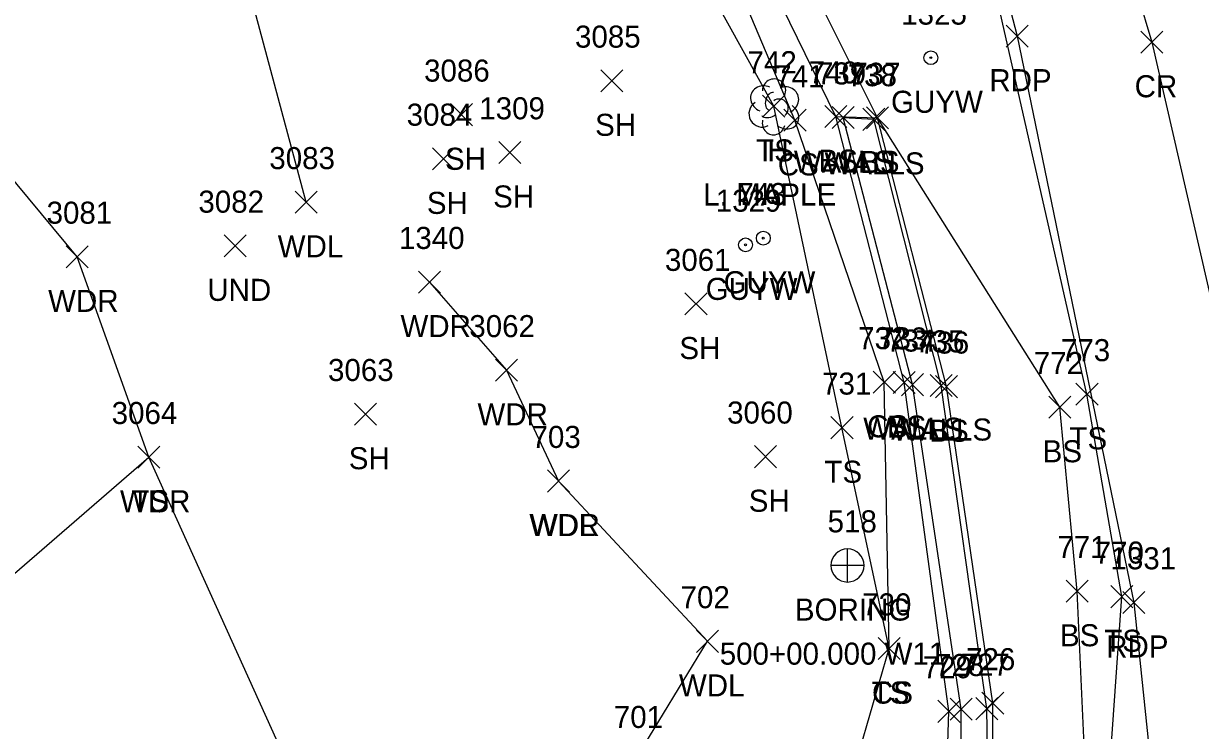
# Model space of a CAD drawing. Extents: x 1509053 to 1511576, y 400838 to 402572.
# Drawn here: x 1509685.4 to 1509792.1, y 401650.1 to 401714.2 of the extents above; entities that cross this region are included whole.
import ezdxf

# ---------------------------------------------------------------- set-up
doc = ezdxf.new("R2010")
doc.units = 0
for name, color, linetype in [('D_A', 7, 'Continuous'), ('D_I', 7, 'Continuous'), ('D_TIC', 7, 'Continuous'), ('G_A', 7, 'Continuous'), ('G_C', 7, 'Continuous'), ('G_I', 7, 'Continuous'), ('GA_P', 7, 'Continuous'), ('L_A', 7, 'Continuous'), ('L_C', 7, 'Continuous'), ('L_I', 7, 'Continuous'), ('L_TIC', 7, 'Continuous'), ('LAWA', 7, 'Continuous'), ('LELB', 7, 'Continuous'), ('LTD', 7, 'Continuous'), ('LWS', 7, 'Continuous'), ('P_A', 7, 'Continuous'), ('P_I', 7, 'Continuous'), ('P_TIC', 7, 'Continuous'), ('PET', 7, 'Continuous'), ('PRC', 7, 'Continuous'), ('U_A', 7, 'Continuous'), ('U_I', 7, 'Continuous'), ('UPGW', 7, 'Continuous')]:
    doc.layers.add(name, color=color, linetype=linetype)

msp = doc.modelspace()

# ---------------------------------------------------------------- linework, layer by layer
at = {"layer": 'D_TIC'}
for points in [[(1509703.59, 401693.05), (1509705.59, 401695.05)], [(1509705.59, 401693.05), (1509703.59, 401695.05)]]:
    msp.add_lwpolyline(points, dxfattribs=at)
at = {"layer": 'GA_P'}
for p, q in [((1509760.09, 401665.05), (1509760.09, 401666.55)), ((1509760.09, 401665.05), (1509758.59, 401665.05)), ((1509761.59, 401665.05), (1509760.09, 401665.05)), ((1509760.09, 401663.55), (1509760.09, 401665.05))]:
    msp.add_line(p, q, dxfattribs=at)
for start, end in [(90, 180), (0, 90), (180, 270), (270, 0)]:
    msp.add_arc((1509760.09, 401665.05), 1.5, start, end, dxfattribs=at)
at = {"layer": 'L_TIC'}
for points in [[(1509737.72, 401708.02), (1509739.72, 401710.02)], [(1509739.72, 401708.02), (1509737.72, 401710.02)], [(1509724.11, 401704.94), (1509726.11, 401706.94)], [(1509726.11, 401704.94), (1509724.11, 401706.94)], [(1509752.4, 401705.7), (1509754.4, 401707.7)], [(1509754.4, 401705.7), (1509752.4, 401707.7)], [(1509758.03, 401704.77), (1509760.03, 401706.77)], [(1509760.03, 401704.77), (1509758.03, 401706.77)], [(1509754.33, 401704.43), (1509756.33, 401706.43)], [(1509756.33, 401704.43), (1509754.33, 401706.43)], [(1509758.69, 401704.68), (1509760.69, 401706.68)], [(1509760.69, 401704.68), (1509758.69, 401706.68)], [(1509761.47, 401704.52), (1509763.47, 401706.52)], [(1509763.47, 401704.52), (1509761.47, 401706.52)], [(1509761.8, 401704.65), (1509763.8, 401706.65)], [(1509763.8, 401704.65), (1509761.8, 401706.65)], [(1509722.47, 401700.94), (1509724.47, 401702.94)], [(1509724.47, 401700.94), (1509722.47, 401702.94)], [(1509728.49, 401701.52), (1509730.49, 401703.52)], [(1509730.49, 401701.52), (1509728.49, 401703.52)], [(1509710.02, 401697), (1509712.02, 401699)], [(1509712.02, 401697), (1509710.02, 401699)], [(1509689.26, 401692.05), (1509691.26, 401694.05)], [(1509691.26, 401692.05), (1509689.26, 401694.05)], [(1509721.2, 401689.76), (1509723.2, 401691.76)], [(1509723.2, 401689.76), (1509721.2, 401691.76)], [(1509745.36, 401687.77), (1509747.36, 401689.77)], [(1509747.36, 401687.77), (1509745.36, 401689.77)], [(1509728.19, 401681.76), (1509730.19, 401683.76)], [(1509730.19, 401681.76), (1509728.19, 401683.76)], [(1509762.43, 401680.67), (1509764.43, 401682.67)], [(1509764.43, 401680.67), (1509762.43, 401682.67)], [(1509764.23, 401680.64), (1509766.23, 401682.64)], [(1509766.23, 401680.64), (1509764.23, 401682.64)], [(1509764.98, 401680.45), (1509766.98, 401682.45)], [(1509766.98, 401680.45), (1509764.98, 401682.45)], [(1509767.59, 401680.38), (1509769.59, 401682.38)], [(1509769.59, 401680.38), (1509767.59, 401682.38)], [(1509768.07, 401680.27), (1509770.07, 401682.27)], [(1509770.07, 401680.27), (1509768.07, 401682.27)], [(1509780.8, 401679.58), (1509782.8, 401681.58)], [(1509782.8, 401679.58), (1509780.8, 401681.58)], [(1509778.34, 401678.41), (1509780.34, 401680.41)], [(1509780.34, 401678.41), (1509778.34, 401680.41)], [(1509715.39, 401677.78), (1509717.39, 401679.78)], [(1509717.39, 401677.78), (1509715.39, 401679.78)], [(1509758.59, 401676.55), (1509760.59, 401678.55)], [(1509760.59, 401676.55), (1509758.59, 401678.55)], [(1509695.77, 401673.88), (1509697.77, 401675.88)], [(1509697.77, 401673.88), (1509695.77, 401675.88)], [(1509695.77, 401673.88), (1509697.77, 401675.88)], [(1509697.77, 401673.88), (1509695.77, 401675.88)], [(1509751.65, 401673.92), (1509753.65, 401675.92)], [(1509753.65, 401673.92), (1509751.65, 401675.92)], [(1509732.89, 401671.71), (1509734.89, 401673.71)], [(1509734.89, 401671.71), (1509732.89, 401673.71)], [(1509732.89, 401671.71), (1509734.89, 401673.71)], [(1509734.89, 401671.71), (1509732.89, 401673.71)], [(1509779.91, 401661.72), (1509781.91, 401663.72)], [(1509781.91, 401661.72), (1509779.91, 401663.72)], [(1509783.95, 401661.22), (1509785.95, 401663.22)], [(1509785.95, 401661.22), (1509783.95, 401663.22)], [(1509746.4, 401657.17), (1509748.4, 401659.17)], [(1509748.4, 401657.17), (1509746.4, 401659.17)], [(1509762.87, 401656.52), (1509764.87, 401658.52)], [(1509764.87, 401656.52), (1509762.87, 401658.52)], [(1509762.87, 401656.52), (1509764.87, 401658.52)], [(1509764.87, 401656.52), (1509762.87, 401658.52)], [(1509772.26, 401651.55), (1509774.26, 401653.55)], [(1509774.26, 401651.55), (1509772.26, 401653.55)], [(1509768.29, 401650.82), (1509770.29, 401652.82)], [(1509770.29, 401650.82), (1509768.29, 401652.82)], [(1509769.39, 401651.02), (1509771.39, 401653.02)], [(1509771.39, 401651.02), (1509769.39, 401653.02)], [(1509771.72, 401651.06), (1509773.72, 401653.06)], [(1509773.72, 401651.06), (1509771.72, 401653.06)]]:
    msp.add_lwpolyline(points, dxfattribs=at)
at = {"layer": 'LAWA'}
for points in [[(1509638.88, 401488.13), (1509666.35, 401492.77), (1509693.47, 401489.31), (1509706.73, 401489.66), (1509714.33, 401510.79), (1509715.13, 401545.88), (1509713.34, 401580.23), (1509712.38, 401615.78), (1509710.87, 401643.63), (1509696.77, 401674.88), (1509690.26, 401693.05), (1509667.45, 401720.56), (1509662.48, 401743.44), (1509649.82, 401764.29), (1509628.65, 401784.18), (1509611.29, 401798.2), (1509592.85, 401815.68), (1509576.11, 401831.25), (1509568.72, 401841.78), (1509569.85, 401855.18), (1509582.24, 401868.06), (1509599.14, 401876.59), (1509619.4, 401883.23)], [(1509711.02, 401698), (1509703.28, 401726.89), (1509691.85, 401755.8), (1509687.42, 401782.25), (1509686, 401801.39)], [(1509722.21, 401690.76), (1509729.19, 401682.76), (1509733.89, 401672.71)], [(1509726.93, 401491.97), (1509738.87, 401505.78), (1509741.65, 401534.19), (1509742.92, 401557.34), (1509741.39, 401578.09), (1509745.24, 401603.86), (1509743.92, 401621.55), (1509740.79, 401647.31), (1509747.4, 401658.17), (1509733.89, 401672.71)]]:
    msp.add_lwpolyline(points, dxfattribs=at)
at = {"layer": 'LELB'}
for points in [[(1509773.23, 401624.44), (1509773.26, 401652.55), (1509769.07, 401681.27), (1509762.8, 401705.65), (1509755.11, 401721.11), (1509758.06, 401721.61), (1509756.54, 401726.82), (1509750.91, 401752.16), (1509738, 401786.77), (1509724.07, 401817.58), (1509715.24, 401833.65), (1509705.02, 401848.12), (1509687.56, 401874.43), (1509682.95, 401881.5), (1509682.01, 401883.09), (1509678.34, 401883.46), (1509668.76, 401883.33)], [(1509755.23, 401531.03), (1509759.29, 401552.77), (1509765.02, 401573.72), (1509768.89, 401600.17), (1509768.39, 401615.04), (1509767.46, 401619.69), (1509766.78, 401624.18), (1509765.92, 401630.49), (1509768.74, 401634.34), (1509769.29, 401651.82), (1509765.23, 401681.64), (1509759.03, 401705.77), (1509750.68, 401722.86), (1509752.06, 401726.1), (1509747.7, 401751.42), (1509733.73, 401785.72), (1509720.36, 401816.7), (1509711.77, 401831.6), (1509702.38, 401845.68), (1509682.87, 401874.27), (1509678.54, 401880.58), (1509678.34, 401883.46)], [(1509731.39, 401479.41), (1509744.85, 401504.05), (1509748.4, 401505.28), (1509750.98, 401532.46), (1509751.98, 401551.59), (1509758.3, 401575), (1509758.92, 401604.42), (1509759.53, 401620.15), (1509759.5, 401642.39), (1509763.87, 401657.52), (1509763.43, 401681.67), (1509755.33, 401705.43), (1509747.09, 401724.92), (1509745.86, 401750.35), (1509730.75, 401785.27), (1509718.16, 401815.85), (1509711.77, 401831.6), (1509699.84, 401843.77), (1509676.05, 401879.71), (1509667.99, 401880.98)], [(1509763.87, 401657.52), (1509759.59, 401677.55), (1509753.4, 401706.7), (1509743.52, 401724.58), (1509742.86, 401748.7), (1509727.08, 401784.6), (1509715.61, 401815.7), (1509711.48, 401828.76), (1509697.83, 401839.96), (1509674.9, 401875.7), (1509667.99, 401880.98)], [(1509747.77, 401416.63), (1509750.21, 401428.63), (1509752.14, 401443.01), (1509750.46, 401466.15), (1509760.48, 401503.51), (1509765.49, 401528.65), (1509770.9, 401551.56), (1509776.3, 401572.59), (1509780.48, 401596.32), (1509778.93, 401605.73), (1509782.51, 401627.45), (1509784.95, 401662.22), (1509781.8, 401680.58), (1509772.99, 401719.38), (1509769.17, 401721), (1509769.65, 401723.75), (1509771.91, 401724.32), (1509762.66, 401754.93), (1509756.13, 401775.54), (1509751.07, 401789.41), (1509736.27, 401824.32), (1509727.62, 401840.87), (1509712.26, 401861.01), (1509694.01, 401878.11)], [(1509759.03, 401705.77), (1509762.8, 401705.65)], [(1509779.34, 401679.41), (1509762.8, 401705.65)], [(1509745.54, 401417.2), (1509747.58, 401428.44), (1509752.14, 401443.01), (1509755.83, 401464.96), (1509763.87, 401503), (1509769.15, 401528.1), (1509775.42, 401550.94), (1509779.3, 401571.9), (1509785.18, 401596.41), (1509784.53, 401607.91), (1509782.51, 401627.45), (1509780.91, 401662.72), (1509779.34, 401679.41)], [(1509614.39, 401635.69), (1509632.71, 401636.18), (1509655.2, 401645.18), (1509672.84, 401654.16), (1509696.77, 401674.88)]]:
    msp.add_lwpolyline(points, dxfattribs=at)
at = {"layer": 'LTD'}
msp.add_line((1509753.4, 401706.7), (1509753.4, 401706.7), dxfattribs=at)
msp.add_line((1509753.4, 401706.7), (1509753.4, 401706.7), dxfattribs=at)
msp.add_arc((1509753.44, 401708.13), 1.05, 335.5272, 180.9563, dxfattribs=at)
for centre, major_axis, ratio, start_param, end_param in [((1509752.6, 401707.36), (1.21, -0.51), 0.895232, 1.570796, 4.712389), ((1509753.19, 401707.15), (-0.208, -0.792), 0.645439, 3.141593, 6.283185), ((1509754.44, 401707.28), (-1.14, -0.48), 0.949671, 1.570796, 4.712389), ((1509752.31, 401705.99), (0.58, -1.04), 0.959034, 3.141593, 6.283185), ((1509753.9, 401706.53), (-0.5, 0.667), 0.989748, 3.141593, 6.283185), ((1509754.4, 401705.86), (-1.09, 0.79), 0.841452, 1.570796, 4.712389), ((1509752.94, 401705.95), (-0.625, -0.083), 0.423636, 0, 3.141593), ((1509753.4, 401705.2), (0.26, 1.06), 0.942809, 1.570796, 4.712389)]:
    msp.add_ellipse(centre, major_axis=major_axis, ratio=ratio, start_param=start_param, end_param=end_param, dxfattribs=at)
at = {"layer": 'LWS'}
for points in [[(1509770.33, 401630.75), (1509770.39, 401652.02), (1509765.98, 401681.45), (1509759.69, 401705.68)], [(1509759.69, 401705.68), (1509762.47, 401705.52)], [(1509770.96, 401624.59), (1509771.64, 401625.31), (1509773.14, 401625.41), (1509772.72, 401652.06), (1509768.59, 401681.38), (1509762.47, 401705.52)]]:
    msp.add_lwpolyline(points, dxfattribs=at)
at = {"layer": 'P_TIC'}
for points in [[(1509774.46, 401712.07), (1509776.46, 401714.07)], [(1509776.46, 401712.07), (1509774.46, 401714.07)], [(1509786.69, 401711.52), (1509788.69, 401713.52)], [(1509788.69, 401711.52), (1509786.69, 401713.52)], [(1509785.06, 401660.7), (1509787.05, 401662.7)], [(1509787.05, 401660.7), (1509785.06, 401662.7)]]:
    msp.add_lwpolyline(points, dxfattribs=at)
at = {"layer": 'PET'}
msp.add_lwpolyline([(1509690.27, 401895.46), (1509701.64, 401882.87), (1509726.68, 401848.01), (1509747.74, 401803.41), (1509763.81, 401758.01), (1509775.46, 401713.07), (1509786.05, 401661.7), (1509787.8, 401644.85), (1509788.16, 401621.99), (1509786.62, 401596.26), (1509780.1, 401566.45), (1509768.35, 401517.81), (1509758.18, 401467.69), (1509749.79, 401418)], dxfattribs=at)
at = {"layer": 'PRC'}
msp.add_lwpolyline([(1509707.24, 401894.16), (1509736.22, 401853.25), (1509757.1, 401807.74), (1509773.38, 401760.44), (1509787.69, 401712.52), (1509798.93, 401663.6)], dxfattribs=at)
at = {"layer": 'UPGW'}
for centre, radius in [((1509767.65, 401711.11), 0.625), ((1509767.65, 401711.11), 0.0833), ((1509752.46, 401694.74), 0.625), ((1509750.85, 401694.13), 0.625), ((1509750.85, 401694.13), 0.0833), ((1509752.46, 401694.74), 0.0833)]:
    msp.add_circle(centre, radius, dxfattribs=at)

# ---------------------------------------------------------------- texts
at = {"layer": 'D_A'}
msp.add_text('UND', height=2, dxfattribs=at).set_placement((1509702.06, 401689.05))
at = {"layer": 'D_I'}
msp.add_text('3082', height=2, dxfattribs=at).set_placement((1509701.25, 401697.05))
at = {"layer": 'G_A'}
msp.add_text('BORING', height=2, dxfattribs=at).set_placement((1509755.32, 401660.05))
at = {"layer": 'G_C'}
msp.add_text('500+00.000 W11', height=2, dxfattribs=at).set_placement((1509748.51, 401656.05))
at = {"layer": 'G_I'}
msp.add_text('518', height=2, dxfattribs=at).set_placement((1509758.29, 401668.05))
at = {"layer": 'L_A'}
for s, p in [('SH', (1509737.21, 401704.02)), ('TS', (1509751.81, 401701.7)), ('H', (1509752.83, 401701.7)), ('SH', (1509723.6, 401700.94)), ('WALLS', (1509755.23, 401700.68)), ('BS', (1509757.47, 401700.77)), ('WALLS', (1509758.01, 401700.52)), ('BS', (1509761.24, 401700.65)), ('CS', (1509753.77, 401700.43)), ('SH', (1509727.97, 401697.52)), ('SH', (1509721.96, 401696.94)), ('WDL', (1509708.44, 401693)), ('WDR', (1509687.63, 401688.05)), ('WDR', (1509719.57, 401685.76)), ('SH', (1509744.85, 401683.77)), ('WDR', (1509726.55, 401677.76)), ('WALLS', (1509761.52, 401676.45)), ('CS', (1509761.87, 401676.67)), ('BS', (1509763.67, 401676.64)), ('WALLS', (1509764.13, 401676.38)), ('BS', (1509767.51, 401676.27)), ('TS', (1509780.21, 401675.58)), ('BS', (1509777.78, 401674.41)), ('SH', (1509714.88, 401673.78)), ('TS', (1509758, 401672.55)), ('WDR', (1509694.14, 401669.88)), ('TS', (1509695.18, 401669.88)), ('SH', (1509751.14, 401669.92)), ('WDR', (1509731.25, 401667.71)), ('WDL', (1509731.31, 401667.71)), ('BS', (1509779.35, 401657.72)), ('TS', (1509783.36, 401657.22)), ('WDL', (1509744.81, 401653.17)), ('TS', (1509762.28, 401652.52)), ('CS', (1509762.31, 401652.52))]:
    msp.add_text(s, height=2, dxfattribs=at).set_placement(p)
at = {"layer": 'L_C'}
msp.add_text('L. MAPLE', height=2, dxfattribs=at).set_placement((1509747.02, 401697.7))
at = {"layer": 'L_I'}
for s, p in [('3085', (1509735.39, 401712.02)), ('742', (1509751.03, 401709.7)), ('742', (1509751.03, 401709.7)), ('3086', (1509721.71, 401708.94)), ('741', (1509753.54, 401708.43)), ('740', (1509756.58, 401708.77)), ('739', (1509757.32, 401708.68)), ('738', (1509760.11, 401708.52)), ('737', (1509760.44, 401708.65)), ('3084', (1509720.13, 401704.94)), ('1309', (1509726.71, 401705.52)), ('3083', (1509707.68, 401701)), ('3081', (1509687.49, 401696.05)), ('1340', (1509719.43, 401693.76)), ('3061', (1509743.54, 401691.77)), ('3062', (1509725.81, 401685.76)), ('732', (1509761.06, 401684.67)), ('733', (1509762.86, 401684.64)), ('734', (1509763.61, 401684.45)), ('735', (1509766.23, 401684.38)), ('736', (1509766.66, 401684.27)), ('773', (1509779.44, 401683.58)), ('772', (1509776.98, 401682.41)), ('3063', (1509713, 401681.78)), ('731', (1509757.79, 401680.55)), ('3064', (1509693.39, 401677.88)), ('3064', (1509693.39, 401677.88)), ('3060', (1509749.18, 401677.92)), ('703', (1509731.45, 401675.71)), ('703', (1509731.45, 401675.71)), ('771', (1509779.12, 401665.72)), ('770', (1509782.5, 401665.22)), ('702', (1509744.96, 401661.17)), ('730', (1509761.42, 401660.52)), ('730', (1509761.42, 401660.52)), ('729', (1509766.92, 401654.82)), ('728', (1509768.03, 401655.02)), ('727', (1509770.35, 401655.06)), ('726', (1509770.84, 401655.55)), ('701', (1509738.91, 401650.31))]:
    msp.add_text(s, height=2, dxfattribs=at).set_placement(p)
at = {"layer": 'P_A'}
for s, p in [('RDP', (1509772.95, 401708.07)), ('CR', (1509786.12, 401707.52)), ('RDP', (1509783.54, 401656.7))]:
    msp.add_text(s, height=2, dxfattribs=at).set_placement(p)
at = {"layer": 'P_I'}
msp.add_text('1331', height=2, dxfattribs=at).set_placement((1509783.93, 401664.7))
at = {"layer": 'U_A'}
for p in [(1509764.04, 401706.11), (1509747.24, 401689.14), (1509748.86, 401689.74)]:
    msp.add_text('GUYW', height=2, dxfattribs=at).set_placement(p)
at = {"layer": 'U_I'}
for s, p in [('1325', (1509764.96, 401714.11)), ('743', (1509750.1, 401697.74)), ('1329', (1509748.15, 401697.14))]:
    msp.add_text(s, height=2, dxfattribs=at).set_placement(p)

doc.saveas('drawing.dxf')
